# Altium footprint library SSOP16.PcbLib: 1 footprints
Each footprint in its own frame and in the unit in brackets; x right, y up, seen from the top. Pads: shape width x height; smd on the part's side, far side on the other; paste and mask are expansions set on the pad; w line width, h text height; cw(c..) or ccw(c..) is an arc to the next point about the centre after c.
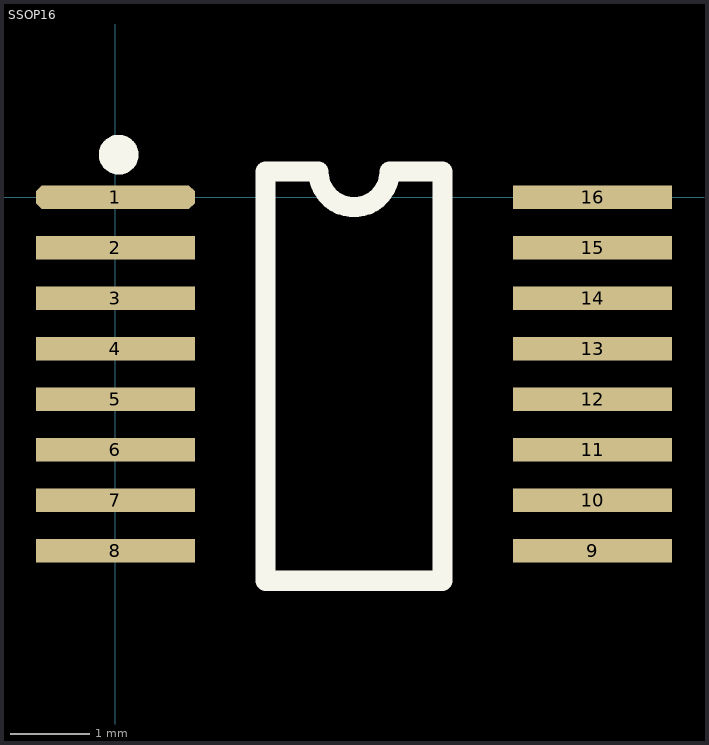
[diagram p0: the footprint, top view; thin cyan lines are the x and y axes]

## SSOP16 [mm] "SOP, 16-Leads, Body 5.0x4.0mm (max), Pitch 0.63mm, IPC Medium Density"
height 1.75
pads (16):
  oct 2x0.3 smd: 1(0,0)
  rect 2x0.3 smd: 2(0,-0.635) 3(0,-1.27) 4(0,-1.905) 5(0,-2.54) 6(0,-3.175) 7(0,-3.81) 8(0,-4.445) 9(6,-4.445) 10(6,-3.81) 11(6,-3.175) 12(6,-2.54) 13(6,-1.905) 14(6,-1.27) 15(6,-0.635) 16(6,0)
Top Overlay:
  circle w0.25: c0.042,0.534 r0.125
  lines w0.254: 1.889,-4.822 1.889,0.322 2.553,0.322 ccw(c3,0.322) 3.447,0.322 4.111,0.322 4.111,-4.822 1.889,-4.822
